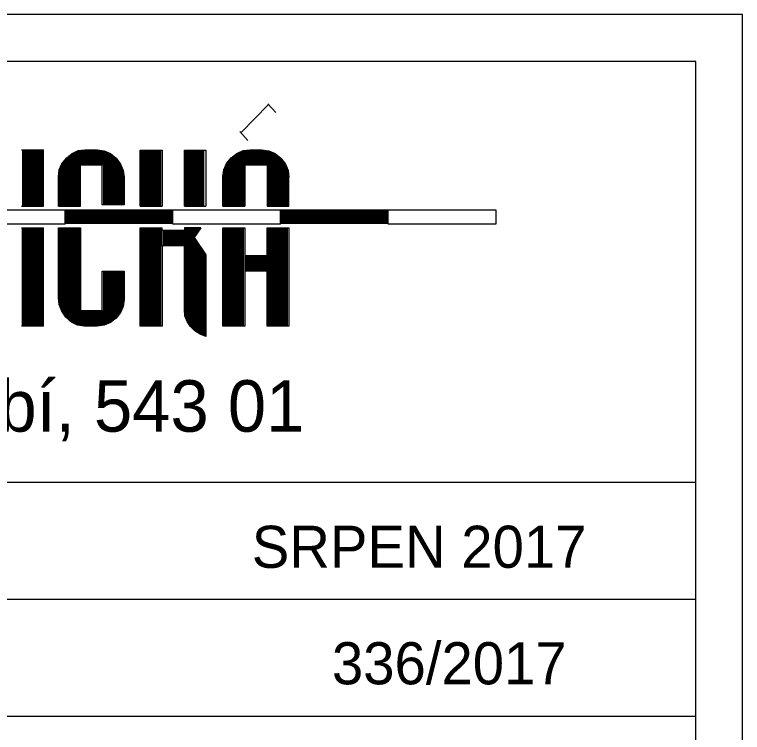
# Model space of a CAD drawing. Extents: x -651478 to -651308, y -994378 to -994071.
# Drawn here: x -651404.16 to -651397.94, y -994317.66 to -994311.53 of the extents above; entities that cross this region are included whole.
import ezdxf

# ---------------------------------------------------------------- set-up
doc = ezdxf.new("R2010")
doc.units = 0
doc.layers.add('rezy', color=7, linetype='Continuous')

msp = doc.modelspace()

# ---------------------------------------------------------------- linework, layer by layer
at = {"layer": 'rezy'}
for p, q in [((-651397.936, -994311.527), (-651431.936, -994311.527)), ((-651397.936, -994324.527), (-651397.936, -994311.527)), ((-651398.336, -994311.927), (-651410.636, -994311.927)), ((-651398.336, -994315.527), (-651398.336, -994311.927)), ((-651401.99, -994312.297), (-651402.228, -994312.537)), ((-651401.996, -994312.29), (-651401.927, -994312.363)), ((-651402.166, -994312.604), (-651402.235, -994312.528)), ((-651404.103, -994312.683), (-651403.914, -994312.683)), ((-651404.093, -994313.166), (-651404.093, -994312.683)), ((-651404.083, -994313.166), (-651404.083, -994312.683)), ((-651404.072, -994313.166), (-651404.072, -994312.683)), ((-651404.062, -994313.166), (-651404.062, -994312.683)), ((-651404.052, -994313.166), (-651404.052, -994312.683)), ((-651404.041, -994313.166), (-651404.041, -994312.683)), ((-651404.031, -994313.166), (-651404.031, -994312.683)), ((-651404.02, -994313.166), (-651404.02, -994312.683)), ((-651404.01, -994313.166), (-651404.01, -994312.683)), ((-651404, -994313.166), (-651404, -994312.683)), ((-651403.989, -994313.166), (-651403.989, -994312.683)), ((-651403.979, -994313.166), (-651403.979, -994312.683)), ((-651403.968, -994313.166), (-651403.968, -994312.683)), ((-651403.958, -994313.166), (-651403.958, -994312.683)), ((-651403.948, -994313.166), (-651403.948, -994312.683)), ((-651403.937, -994313.166), (-651403.937, -994312.683)), ((-651403.927, -994313.166), (-651403.927, -994312.683)), ((-651403.916, -994313.166), (-651403.916, -994312.683)), ((-651403.67, -994312.714), (-651403.618, -994312.69)), ((-651403.663, -994313.166), (-651403.663, -994312.711)), ((-651403.652, -994313.166), (-651403.652, -994312.706)), ((-651403.642, -994313.166), (-651403.642, -994312.701)), ((-651403.632, -994313.166), (-651403.632, -994312.697)), ((-651403.621, -994313.166), (-651403.621, -994312.692)), ((-651403.618, -994312.69), (-651403.561, -994312.683)), ((-651403.611, -994313.166), (-651403.611, -994312.689)), ((-651403.611, -994312.689), (-651403.611, -994312.823)), ((-651403.6, -994312.688), (-651403.6, -994312.815)), ((-651403.59, -994312.687), (-651403.59, -994312.815)), ((-651403.58, -994312.685), (-651403.58, -994312.815)), ((-651403.569, -994312.684), (-651403.569, -994312.815)), ((-651403.561, -994312.683), (-651403.452, -994312.683)), ((-651403.559, -994312.683), (-651403.559, -994312.815)), ((-651403.548, -994312.683), (-651403.548, -994312.815)), ((-651403.538, -994312.683), (-651403.538, -994312.815)), ((-651403.528, -994312.683), (-651403.528, -994312.815)), ((-651403.517, -994312.683), (-651403.517, -994312.815)), ((-651403.507, -994312.683), (-651403.507, -994312.815)), ((-651403.496, -994312.683), (-651403.496, -994312.815)), ((-651403.486, -994312.683), (-651403.486, -994312.815)), ((-651403.476, -994312.683), (-651403.476, -994312.815)), ((-651403.465, -994312.683), (-651403.465, -994312.815)), ((-651403.455, -994312.683), (-651403.455, -994312.815)), ((-651403.452, -994312.683), (-651403.395, -994312.691)), ((-651403.444, -994312.684), (-651403.444, -994312.815)), ((-651403.434, -994312.685), (-651403.434, -994312.815)), ((-651403.424, -994312.687), (-651403.424, -994312.815)), ((-651403.413, -994312.688), (-651403.413, -994312.815)), ((-651403.403, -994312.69), (-651403.403, -994313.154)), ((-651403.395, -994312.691), (-651403.343, -994312.715)), ((-651403.392, -994312.692), (-651403.392, -994313.154)), ((-651403.382, -994312.697), (-651403.382, -994313.154)), ((-651403.372, -994312.702), (-651403.372, -994313.154)), ((-651403.361, -994312.706), (-651403.361, -994313.154)), ((-651403.351, -994312.711), (-651403.351, -994313.154)), ((-651403.089, -994313.166), (-651403.089, -994312.686)), ((-651403.089, -994312.686), (-651402.9, -994312.686)), ((-651403.079, -994313.166), (-651403.079, -994312.686)), ((-651403.068, -994313.166), (-651403.068, -994312.686)), ((-651403.058, -994313.166), (-651403.058, -994312.686)), ((-651403.048, -994313.166), (-651403.048, -994312.686)), ((-651403.037, -994313.166), (-651403.037, -994312.686)), ((-651403.027, -994313.166), (-651403.027, -994312.686)), ((-651403.016, -994313.166), (-651403.016, -994312.686)), ((-651403.006, -994313.166), (-651403.006, -994312.686)), ((-651402.996, -994313.166), (-651402.996, -994312.686)), ((-651402.985, -994313.166), (-651402.985, -994312.686)), ((-651402.975, -994313.166), (-651402.975, -994312.686)), ((-651402.964, -994313.166), (-651402.964, -994312.686)), ((-651402.954, -994313.166), (-651402.954, -994312.686)), ((-651402.944, -994313.166), (-651402.944, -994312.686)), ((-651402.933, -994313.166), (-651402.933, -994312.686)), ((-651402.923, -994313.166), (-651402.923, -994312.686)), ((-651402.912, -994313.166), (-651402.912, -994312.686)), ((-651402.9, -994312.686), (-651402.9, -994313.166)), ((-651402.71, -994313.166), (-651402.71, -994312.686)), ((-651402.71, -994312.686), (-651402.527, -994312.686)), ((-651402.7, -994313.166), (-651402.7, -994312.686)), ((-651402.69, -994313.166), (-651402.69, -994312.686)), ((-651402.679, -994313.166), (-651402.679, -994312.686)), ((-651402.669, -994313.166), (-651402.669, -994312.686)), ((-651402.658, -994313.166), (-651402.658, -994312.686)), ((-651402.648, -994313.166), (-651402.648, -994312.686)), ((-651402.638, -994313.166), (-651402.638, -994312.686)), ((-651402.627, -994313.166), (-651402.627, -994312.686)), ((-651402.617, -994313.166), (-651402.617, -994312.686)), ((-651402.606, -994313.166), (-651402.606, -994312.686)), ((-651402.596, -994313.166), (-651402.596, -994312.686)), ((-651402.586, -994313.166), (-651402.586, -994312.686)), ((-651402.575, -994313.166), (-651402.575, -994312.686)), ((-651402.565, -994313.166), (-651402.565, -994312.686)), ((-651402.554, -994313.166), (-651402.554, -994312.686)), ((-651402.544, -994313.166), (-651402.544, -994312.686)), ((-651402.527, -994312.686), (-651402.527, -994313.166)), ((-651402.262, -994312.714), (-651402.208, -994312.69)), ((-651402.256, -994313.166), (-651402.256, -994312.711)), ((-651402.246, -994313.166), (-651402.246, -994312.707)), ((-651402.235, -994313.166), (-651402.235, -994312.702)), ((-651402.225, -994313.166), (-651402.225, -994312.698)), ((-651402.215, -994313.166), (-651402.215, -994312.693)), ((-651402.208, -994312.69), (-651402.15, -994312.683)), ((-651402.204, -994313.166), (-651402.204, -994312.69)), ((-651402.194, -994313.166), (-651402.194, -994312.688)), ((-651402.194, -994312.688), (-651402.194, -994312.809)), ((-651402.183, -994312.687), (-651402.183, -994312.815)), ((-651402.173, -994312.686), (-651402.173, -994312.815)), ((-651402.163, -994312.684), (-651402.163, -994312.815)), ((-651402.152, -994312.683), (-651402.152, -994312.815)), ((-651402.15, -994312.683), (-651402.046, -994312.683)), ((-651402.142, -994312.683), (-651402.142, -994312.815)), ((-651402.131, -994312.683), (-651402.131, -994312.815)), ((-651402.121, -994312.683), (-651402.121, -994312.815)), ((-651402.111, -994312.683), (-651402.111, -994312.815)), ((-651402.1, -994312.683), (-651402.1, -994312.815)), ((-651402.09, -994312.683), (-651402.09, -994312.815)), ((-651402.079, -994312.683), (-651402.079, -994312.815)), ((-651402.069, -994312.683), (-651402.069, -994312.815)), ((-651402.059, -994312.683), (-651402.059, -994312.815)), ((-651402.048, -994312.683), (-651402.048, -994312.815)), ((-651402.046, -994312.683), (-651401.987, -994312.691)), ((-651402.038, -994312.684), (-651402.038, -994312.815)), ((-651402.027, -994312.685), (-651402.027, -994312.815)), ((-651402.017, -994312.686), (-651402.017, -994312.815)), ((-651402.007, -994312.688), (-651402.007, -994312.815)), ((-651401.996, -994312.689), (-651401.996, -994313.166)), ((-651401.987, -994312.691), (-651401.934, -994312.715)), ((-651401.986, -994312.691), (-651401.986, -994313.166)), ((-651401.975, -994312.696), (-651401.975, -994313.166)), ((-651401.965, -994312.701), (-651401.965, -994313.166)), ((-651401.955, -994312.705), (-651401.955, -994313.166)), ((-651401.944, -994312.71), (-651401.944, -994313.166)), ((-651403.757, -994312.803), (-651403.719, -994312.754)), ((-651403.725, -994313.166), (-651403.725, -994312.762)), ((-651403.719, -994312.754), (-651403.67, -994312.714)), ((-651403.715, -994313.166), (-651403.715, -994312.75)), ((-651403.704, -994313.166), (-651403.704, -994312.742)), ((-651403.694, -994313.166), (-651403.694, -994312.733)), ((-651403.684, -994313.166), (-651403.684, -994312.725)), ((-651403.673, -994313.166), (-651403.673, -994312.716)), ((-651403.343, -994312.715), (-651403.294, -994312.756)), ((-651403.34, -994312.717), (-651403.34, -994313.154)), ((-651403.33, -994312.726), (-651403.33, -994313.154)), ((-651403.32, -994312.734), (-651403.32, -994313.154)), ((-651403.309, -994312.743), (-651403.309, -994313.154)), ((-651403.299, -994312.752), (-651403.299, -994313.154)), ((-651403.294, -994312.756), (-651403.256, -994312.806)), ((-651403.288, -994312.763), (-651403.288, -994313.154)), ((-651402.35, -994312.801), (-651402.311, -994312.753)), ((-651402.319, -994313.166), (-651402.319, -994312.762)), ((-651402.311, -994312.753), (-651402.262, -994312.714)), ((-651402.308, -994313.166), (-651402.308, -994312.75)), ((-651402.298, -994313.166), (-651402.298, -994312.742)), ((-651402.287, -994313.166), (-651402.287, -994312.734)), ((-651402.277, -994313.166), (-651402.277, -994312.726)), ((-651402.267, -994313.166), (-651402.267, -994312.717)), ((-651401.934, -994312.715), (-651401.885, -994312.755)), ((-651401.934, -994312.715), (-651401.934, -994313.166)), ((-651401.923, -994312.723), (-651401.923, -994313.166)), ((-651401.913, -994312.732), (-651401.913, -994313.166)), ((-651401.903, -994312.74), (-651401.903, -994313.166)), ((-651401.892, -994312.749), (-651401.892, -994313.166)), ((-651401.885, -994312.755), (-651401.846, -994312.805)), ((-651401.882, -994312.758), (-651401.882, -994313.166)), ((-651401.871, -994312.772), (-651401.871, -994313.166)), ((-651403.78, -994312.855), (-651403.757, -994312.803)), ((-651403.767, -994313.166), (-651403.767, -994312.825)), ((-651403.756, -994313.166), (-651403.756, -994312.802)), ((-651403.746, -994313.166), (-651403.746, -994312.789)), ((-651403.736, -994313.166), (-651403.736, -994312.775)), ((-651403.598, -994313.166), (-651403.598, -994312.815)), ((-651403.413, -994312.815), (-651403.598, -994312.815)), ((-651403.413, -994313.154), (-651403.413, -994312.815)), ((-651403.278, -994312.777), (-651403.278, -994313.154)), ((-651403.268, -994312.791), (-651403.268, -994313.154)), ((-651403.257, -994312.804), (-651403.257, -994313.154)), ((-651403.256, -994312.806), (-651403.233, -994312.86)), ((-651403.247, -994312.828), (-651403.247, -994313.154)), ((-651402.373, -994312.854), (-651402.35, -994312.801)), ((-651402.36, -994313.166), (-651402.36, -994312.825)), ((-651402.35, -994313.166), (-651402.35, -994312.801)), ((-651402.339, -994313.166), (-651402.339, -994312.788)), ((-651402.329, -994313.166), (-651402.329, -994312.775)), ((-651402.192, -994312.815), (-651402.192, -994313.166)), ((-651402.002, -994312.815), (-651402.192, -994312.815)), ((-651402.002, -994312.815), (-651402.002, -994313.166)), ((-651401.861, -994312.785), (-651401.861, -994313.166)), ((-651401.851, -994312.799), (-651401.851, -994313.166)), ((-651401.846, -994312.805), (-651401.823, -994312.859)), ((-651401.84, -994312.818), (-651401.84, -994313.166)), ((-651403.788, -994312.911), (-651403.78, -994312.855)), ((-651403.777, -994313.166), (-651403.777, -994312.849)), ((-651403.236, -994312.852), (-651403.236, -994313.154)), ((-651403.233, -994312.86), (-651403.225, -994312.917)), ((-651402.381, -994312.911), (-651402.373, -994312.854)), ((-651402.371, -994313.166), (-651402.371, -994312.848)), ((-651401.83, -994312.842), (-651401.83, -994313.166)), ((-651401.823, -994312.859), (-651401.815, -994312.917)), ((-651401.819, -994312.883), (-651401.819, -994313.166)), ((-651403.788, -994313.166), (-651403.788, -994312.911)), ((-651403.225, -994312.917), (-651403.225, -994313.154)), ((-651402.381, -994313.166), (-651402.381, -994312.911)), ((-651401.815, -994313.166), (-651401.815, -994312.917)), ((-651404.651, -994313.197), (-651403.73, -994313.197)), ((-651404.103, -994313.166), (-651403.914, -994313.166)), ((-651403.788, -994313.166), (-651403.598, -994313.166)), ((-651403.73, -994313.197), (-651402.808, -994313.197)), ((-651403.73, -994313.32), (-651403.73, -994313.197)), ((-651403.73, -994313.207), (-651402.808, -994313.207)), ((-651403.225, -994313.154), (-651403.413, -994313.154)), ((-651403.089, -994313.166), (-651402.9, -994313.166)), ((-651402.808, -994313.197), (-651401.887, -994313.197)), ((-651402.808, -994313.32), (-651402.808, -994313.197)), ((-651402.71, -994313.166), (-651402.527, -994313.166)), ((-651402.381, -994313.166), (-651402.192, -994313.166)), ((-651402.002, -994313.166), (-651401.815, -994313.166)), ((-651401.887, -994313.197), (-651400.966, -994313.197)), ((-651401.887, -994313.32), (-651401.887, -994313.197)), ((-651401.887, -994313.207), (-651400.966, -994313.207)), ((-651400.967, -994313.197), (-651400.046, -994313.197)), ((-651400.967, -994313.32), (-651400.967, -994313.197)), ((-651400.046, -994313.197), (-651400.046, -994313.32)), ((-651403.73, -994313.218), (-651402.808, -994313.218)), ((-651403.73, -994313.228), (-651402.808, -994313.228)), ((-651403.73, -994313.238), (-651402.808, -994313.238)), ((-651403.73, -994313.249), (-651402.808, -994313.249)), ((-651403.73, -994313.259), (-651402.808, -994313.259)), ((-651403.73, -994313.27), (-651402.808, -994313.27)), ((-651401.887, -994313.218), (-651400.966, -994313.218)), ((-651401.887, -994313.228), (-651400.966, -994313.228)), ((-651401.887, -994313.238), (-651400.966, -994313.238)), ((-651401.887, -994313.249), (-651400.966, -994313.249)), ((-651401.887, -994313.259), (-651400.966, -994313.259)), ((-651401.887, -994313.27), (-651400.966, -994313.27)), ((-651403.73, -994313.32), (-651404.651, -994313.32)), ((-651403.73, -994313.28), (-651402.808, -994313.28)), ((-651403.73, -994313.29), (-651402.808, -994313.29)), ((-651403.73, -994313.301), (-651402.808, -994313.301)), ((-651403.73, -994313.311), (-651402.808, -994313.311)), ((-651401.887, -994313.32), (-651402.808, -994313.32)), ((-651401.887, -994313.28), (-651400.966, -994313.28)), ((-651401.887, -994313.29), (-651400.966, -994313.29)), ((-651401.887, -994313.301), (-651400.966, -994313.301)), ((-651401.887, -994313.311), (-651400.966, -994313.311)), ((-651400.046, -994313.32), (-651400.967, -994313.32)), ((-651404.103, -994313.35), (-651403.914, -994313.35)), ((-651404.096, -994313.35), (-651404.096, -994314.19)), ((-651404.085, -994313.35), (-651404.085, -994314.19)), ((-651404.075, -994313.35), (-651404.075, -994314.19)), ((-651404.065, -994313.35), (-651404.065, -994314.19)), ((-651404.054, -994313.35), (-651404.054, -994314.19)), ((-651404.044, -994313.35), (-651404.044, -994314.19)), ((-651404.033, -994313.35), (-651404.033, -994314.19)), ((-651404.023, -994313.35), (-651404.023, -994314.19)), ((-651404.013, -994313.35), (-651404.013, -994314.19)), ((-651404.002, -994313.35), (-651404.002, -994314.19)), ((-651403.992, -994313.35), (-651403.992, -994314.19)), ((-651403.981, -994313.35), (-651403.981, -994314.19)), ((-651403.971, -994313.35), (-651403.971, -994314.19)), ((-651403.961, -994313.35), (-651403.961, -994314.19)), ((-651403.95, -994313.35), (-651403.95, -994314.19)), ((-651403.94, -994313.35), (-651403.94, -994314.19)), ((-651403.929, -994313.35), (-651403.929, -994314.19)), ((-651403.919, -994313.35), (-651403.919, -994314.19)), ((-651403.788, -994313.947), (-651403.788, -994313.35)), ((-651403.788, -994313.35), (-651403.598, -994313.35)), ((-651403.777, -994314.015), (-651403.777, -994313.35)), ((-651403.767, -994314.042), (-651403.767, -994313.35)), ((-651403.756, -994314.066), (-651403.756, -994313.35)), ((-651403.746, -994314.081), (-651403.746, -994313.35)), ((-651403.736, -994314.096), (-651403.736, -994313.35)), ((-651403.725, -994314.111), (-651403.725, -994313.35)), ((-651403.725, -994314.081), (-651403.725, -994313.35)), ((-651403.715, -994314.122), (-651403.715, -994313.35)), ((-651403.704, -994314.131), (-651403.704, -994313.35)), ((-651403.694, -994314.14), (-651403.694, -994313.35)), ((-651403.684, -994314.15), (-651403.684, -994313.35)), ((-651403.673, -994314.158), (-651403.673, -994313.35)), ((-651403.663, -994314.163), (-651403.663, -994313.35)), ((-651403.652, -994314.168), (-651403.652, -994313.35)), ((-651403.642, -994314.173), (-651403.642, -994313.35)), ((-651403.632, -994314.178), (-651403.632, -994313.35)), ((-651403.621, -994314.182), (-651403.621, -994313.35)), ((-651403.611, -994314.183), (-651403.611, -994313.35)), ((-651403.6, -994314.185), (-651403.6, -994313.35)), ((-651403.598, -994313.35), (-651403.598, -994314.056)), ((-651403.089, -994314.19), (-651403.089, -994313.35)), ((-651403.089, -994313.35), (-651402.9, -994313.35)), ((-651403.079, -994314.19), (-651403.079, -994313.35)), ((-651403.068, -994314.19), (-651403.068, -994313.35)), ((-651403.058, -994314.19), (-651403.058, -994313.35)), ((-651403.048, -994314.19), (-651403.048, -994313.35)), ((-651403.037, -994314.19), (-651403.037, -994313.35)), ((-651403.027, -994314.19), (-651403.027, -994313.35)), ((-651403.016, -994314.19), (-651403.016, -994313.35)), ((-651403.006, -994314.19), (-651403.006, -994313.35)), ((-651402.996, -994314.19), (-651402.996, -994313.35)), ((-651402.985, -994314.19), (-651402.985, -994313.35)), ((-651402.975, -994314.19), (-651402.975, -994313.35)), ((-651402.964, -994314.19), (-651402.964, -994313.35)), ((-651402.954, -994314.19), (-651402.954, -994313.35)), ((-651402.944, -994314.19), (-651402.944, -994313.35)), ((-651402.933, -994314.19), (-651402.933, -994313.35)), ((-651402.923, -994314.19), (-651402.923, -994313.35)), ((-651402.912, -994314.19), (-651402.912, -994313.35)), ((-651402.902, -994313.503), (-651402.902, -994313.35)), ((-651402.9, -994313.369), (-651402.9, -994313.35)), ((-651402.9, -994313.369), (-651402.71, -994313.369)), ((-651402.892, -994313.369), (-651402.892, -994313.503)), ((-651402.881, -994313.369), (-651402.881, -994313.503)), ((-651402.871, -994313.369), (-651402.871, -994313.503)), ((-651402.86, -994313.369), (-651402.86, -994313.503)), ((-651402.85, -994313.369), (-651402.85, -994313.503)), ((-651402.84, -994313.369), (-651402.84, -994313.503)), ((-651402.829, -994313.369), (-651402.829, -994313.503)), ((-651402.819, -994313.369), (-651402.819, -994313.503)), ((-651402.808, -994313.369), (-651402.808, -994313.503)), ((-651402.798, -994313.369), (-651402.798, -994313.503)), ((-651402.788, -994313.369), (-651402.788, -994313.503)), ((-651402.777, -994313.369), (-651402.777, -994313.503)), ((-651402.767, -994313.369), (-651402.767, -994313.503)), ((-651402.756, -994313.369), (-651402.756, -994313.503)), ((-651402.746, -994313.369), (-651402.746, -994313.503)), ((-651402.736, -994313.369), (-651402.736, -994313.503)), ((-651402.725, -994313.369), (-651402.725, -994313.503)), ((-651402.715, -994313.369), (-651402.715, -994313.503)), ((-651402.71, -994313.35), (-651402.71, -994313.369)), ((-651402.57, -994313.35), (-651402.71, -994313.35)), ((-651402.704, -994313.35), (-651402.704, -994314.103)), ((-651402.694, -994313.35), (-651402.694, -994314.131)), ((-651402.684, -994313.35), (-651402.684, -994314.155)), ((-651402.673, -994313.35), (-651402.673, -994314.17)), ((-651402.663, -994313.35), (-651402.663, -994314.185)), ((-651402.652, -994313.35), (-651402.652, -994314.198)), ((-651402.642, -994313.35), (-651402.642, -994314.209)), ((-651402.632, -994313.35), (-651402.632, -994314.219)), ((-651402.57, -994313.35), (-651402.626, -994313.434)), ((-651402.621, -994313.428), (-651402.621, -994313.35)), ((-651402.611, -994313.412), (-651402.611, -994313.35)), ((-651402.6, -994313.396), (-651402.6, -994313.35)), ((-651402.59, -994313.38), (-651402.59, -994313.35)), ((-651402.58, -994313.364), (-651402.58, -994313.35)), ((-651402.381, -994314.19), (-651402.381, -994313.35)), ((-651402.381, -994313.35), (-651402.192, -994313.35)), ((-651402.371, -994314.19), (-651402.371, -994313.35)), ((-651402.36, -994314.19), (-651402.36, -994313.35)), ((-651402.35, -994314.19), (-651402.35, -994313.35)), ((-651402.339, -994314.19), (-651402.339, -994313.35)), ((-651402.329, -994314.19), (-651402.329, -994313.35)), ((-651402.319, -994314.19), (-651402.319, -994313.35)), ((-651402.308, -994314.19), (-651402.308, -994313.35)), ((-651402.298, -994314.19), (-651402.298, -994313.35)), ((-651402.287, -994314.19), (-651402.287, -994313.35)), ((-651402.277, -994314.19), (-651402.277, -994313.35)), ((-651402.267, -994314.19), (-651402.267, -994313.35)), ((-651402.256, -994314.19), (-651402.256, -994313.35)), ((-651402.246, -994314.19), (-651402.246, -994313.35)), ((-651402.235, -994314.19), (-651402.235, -994313.35)), ((-651402.225, -994314.19), (-651402.225, -994313.35)), ((-651402.215, -994314.19), (-651402.215, -994313.35)), ((-651402.204, -994314.19), (-651402.204, -994313.35)), ((-651402.192, -994313.35), (-651402.192, -994313.588)), ((-651402.002, -994313.588), (-651402.002, -994313.35)), ((-651402.002, -994313.35), (-651401.815, -994313.35)), ((-651401.996, -994313.35), (-651401.996, -994314.19)), ((-651401.986, -994313.35), (-651401.986, -994314.19)), ((-651401.975, -994313.35), (-651401.975, -994314.19)), ((-651401.965, -994313.35), (-651401.965, -994314.19)), ((-651401.955, -994313.35), (-651401.955, -994314.19)), ((-651401.944, -994313.35), (-651401.944, -994314.19)), ((-651401.934, -994313.35), (-651401.934, -994314.19)), ((-651401.923, -994313.35), (-651401.923, -994314.19)), ((-651401.913, -994313.35), (-651401.913, -994314.19)), ((-651401.903, -994313.35), (-651401.903, -994314.19)), ((-651401.892, -994313.35), (-651401.892, -994314.19)), ((-651401.882, -994313.35), (-651401.882, -994314.19)), ((-651401.871, -994313.35), (-651401.871, -994314.19)), ((-651401.861, -994313.35), (-651401.861, -994314.19)), ((-651401.851, -994313.35), (-651401.851, -994314.19)), ((-651401.84, -994313.35), (-651401.84, -994314.19)), ((-651401.83, -994313.35), (-651401.83, -994314.19)), ((-651401.815, -994313.35), (-651401.815, -994314.19)), ((-651402.626, -994313.434), (-651402.527, -994313.58)), ((-651402.621, -994313.441), (-651402.621, -994314.229)), ((-651402.611, -994313.456), (-651402.611, -994314.237)), ((-651402.71, -994313.503), (-651402.9, -994313.503)), ((-651402.9, -994313.503), (-651402.9, -994314.19)), ((-651402.71, -994314.052), (-651402.71, -994313.503)), ((-651402.6, -994313.471), (-651402.6, -994314.243)), ((-651402.59, -994313.487), (-651402.59, -994314.25)), ((-651402.58, -994313.502), (-651402.58, -994314.257)), ((-651402.569, -994313.518), (-651402.569, -994314.262)), ((-651402.559, -994313.533), (-651402.559, -994314.266)), ((-651402.548, -994313.548), (-651402.548, -994314.27)), ((-651402.538, -994313.564), (-651402.538, -994314.274)), ((-651402.527, -994313.58), (-651402.527, -994314.279)), ((-651402.194, -994313.588), (-651402.194, -994313.72)), ((-651402.192, -994313.588), (-651402.002, -994313.588)), ((-651402.183, -994313.588), (-651402.183, -994313.72)), ((-651402.173, -994313.588), (-651402.173, -994313.72)), ((-651402.163, -994313.588), (-651402.163, -994313.72)), ((-651402.152, -994313.588), (-651402.152, -994313.72)), ((-651402.142, -994313.588), (-651402.142, -994313.72)), ((-651402.131, -994313.588), (-651402.131, -994313.72)), ((-651402.121, -994313.588), (-651402.121, -994313.72)), ((-651402.111, -994313.588), (-651402.111, -994313.72)), ((-651402.1, -994313.588), (-651402.1, -994313.72)), ((-651402.09, -994313.588), (-651402.09, -994313.72)), ((-651402.079, -994313.588), (-651402.079, -994313.72)), ((-651402.069, -994313.588), (-651402.069, -994313.72)), ((-651402.059, -994313.588), (-651402.059, -994313.72)), ((-651402.048, -994313.588), (-651402.048, -994313.72)), ((-651402.038, -994313.588), (-651402.038, -994313.72)), ((-651402.027, -994313.588), (-651402.027, -994313.72)), ((-651402.017, -994313.588), (-651402.017, -994313.72)), ((-651402.007, -994313.588), (-651402.007, -994313.72)), ((-651403.413, -994314.056), (-651403.413, -994313.72)), ((-651403.413, -994313.72), (-651403.225, -994313.72)), ((-651403.403, -994313.72), (-651403.403, -994314.183)), ((-651403.392, -994313.72), (-651403.392, -994314.18)), ((-651403.382, -994313.72), (-651403.382, -994314.176)), ((-651403.372, -994313.72), (-651403.372, -994314.172)), ((-651403.361, -994313.72), (-651403.361, -994314.167)), ((-651403.351, -994313.72), (-651403.351, -994314.163)), ((-651403.34, -994313.72), (-651403.34, -994314.158)), ((-651403.33, -994313.72), (-651403.33, -994314.15)), ((-651403.32, -994313.72), (-651403.32, -994314.142)), ((-651403.309, -994313.72), (-651403.309, -994314.134)), ((-651403.299, -994313.72), (-651403.299, -994314.126)), ((-651403.288, -994313.72), (-651403.288, -994314.115)), ((-651403.278, -994313.72), (-651403.278, -994314.102)), ((-651403.268, -994313.72), (-651403.268, -994314.089)), ((-651403.257, -994313.72), (-651403.257, -994314.077)), ((-651403.247, -994313.72), (-651403.247, -994314.054)), ((-651403.236, -994313.72), (-651403.236, -994314.03)), ((-651403.225, -994313.72), (-651403.225, -994313.963)), ((-651402.002, -994313.72), (-651402.192, -994313.72)), ((-651402.192, -994313.72), (-651402.192, -994314.19)), ((-651402.002, -994314.19), (-651402.002, -994313.72)), ((-651403.78, -994314.007), (-651403.788, -994313.947)), ((-651403.759, -994314.063), (-651403.78, -994314.007)), ((-651403.225, -994313.963), (-651403.233, -994314.022)), ((-651403.723, -994314.115), (-651403.759, -994314.063)), ((-651403.6, -994314.054), (-651403.6, -994314.185)), ((-651403.598, -994314.056), (-651403.413, -994314.056)), ((-651403.59, -994314.056), (-651403.59, -994314.186)), ((-651403.58, -994314.056), (-651403.58, -994314.188)), ((-651403.569, -994314.056), (-651403.569, -994314.189)), ((-651403.559, -994314.056), (-651403.559, -994314.19)), ((-651403.548, -994314.056), (-651403.548, -994314.19)), ((-651403.538, -994314.056), (-651403.538, -994314.19)), ((-651403.528, -994314.056), (-651403.528, -994314.19)), ((-651403.517, -994314.056), (-651403.517, -994314.19)), ((-651403.507, -994314.056), (-651403.507, -994314.19)), ((-651403.496, -994314.056), (-651403.496, -994314.19)), ((-651403.486, -994314.056), (-651403.486, -994314.19)), ((-651403.476, -994314.056), (-651403.476, -994314.19)), ((-651403.465, -994314.056), (-651403.465, -994314.19)), ((-651403.455, -994314.056), (-651403.455, -994314.19)), ((-651403.444, -994314.056), (-651403.444, -994314.188)), ((-651403.434, -994314.056), (-651403.434, -994314.187)), ((-651403.424, -994314.056), (-651403.424, -994314.186)), ((-651403.413, -994314.056), (-651403.413, -994314.184)), ((-651403.256, -994314.075), (-651403.294, -994314.123)), ((-651403.233, -994314.022), (-651403.256, -994314.075)), ((-651402.705, -994314.103), (-651402.71, -994314.052)), ((-651403.676, -994314.156), (-651403.723, -994314.115)), ((-651403.294, -994314.123), (-651403.343, -994314.16)), ((-651402.687, -994314.15), (-651402.705, -994314.103)), ((-651403.914, -994314.19), (-651404.103, -994314.19)), ((-651403.624, -994314.181), (-651403.676, -994314.156)), ((-651403.567, -994314.19), (-651403.624, -994314.181)), ((-651403.456, -994314.19), (-651403.567, -994314.19)), ((-651403.397, -994314.182), (-651403.456, -994314.19)), ((-651403.343, -994314.16), (-651403.397, -994314.182)), ((-651402.9, -994314.19), (-651403.089, -994314.19)), ((-651402.657, -994314.194), (-651402.687, -994314.15)), ((-651402.619, -994314.231), (-651402.657, -994314.194)), ((-651402.192, -994314.19), (-651402.381, -994314.19)), ((-651401.815, -994314.19), (-651402.002, -994314.19)), ((-651402.576, -994314.259), (-651402.619, -994314.231)), ((-651402.527, -994314.279), (-651402.576, -994314.259)), ((-651398.336, -994315.527), (-651410.636, -994315.527)), ((-651398.336, -994321.527), (-651398.336, -994315.527)), ((-651398.336, -994316.527), (-651410.636, -994316.527)), ((-651398.336, -994317.527), (-651410.636, -994317.527))]:
    msp.add_line(p, q, dxfattribs=at)

# ---------------------------------------------------------------- texts
for s, height, p in [('Fügnerova 42, Vrchlabí, 543 01', 0.44, (-651409.9263, -994315.093)), ('SRPEN 2017', 0.36, (-651402.1334, -994316.257)), ('336/2017', 0.36, (-651401.4477, -994317.253))]:
    msp.add_text(s, height=height, dxfattribs=at).set_placement(p)

doc.saveas('drawing.dxf')
